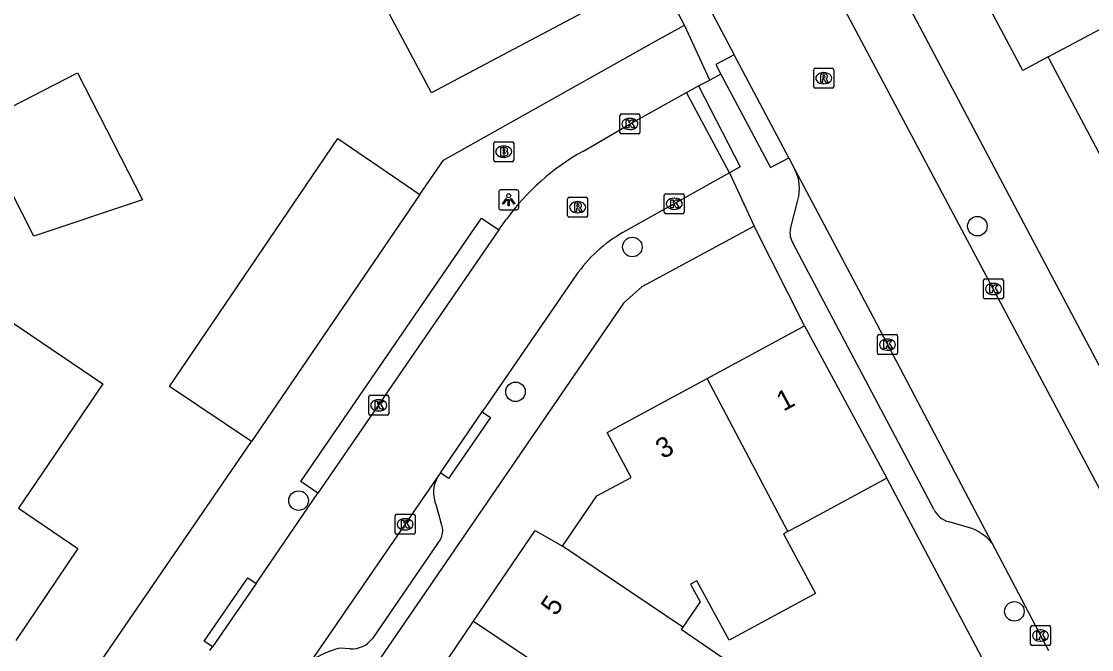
# Model space of a CAD drawing. Extents: x 157321 to 158827, y 386650 to 388532.
# Drawn here: x 157676.1 to 157729.7, y 387594.2 to 387625.6 of the extents above; entities that cross this region are included whole.
import ezdxf

# ---------------------------------------------------------------- set-up
doc = ezdxf.new("R2010")
doc.units = 0
for name, color, linetype in [('IMGEO_Boom', 7, 'Continuous'), ('IMGEO_Brandkraan', 7, 'Continuous'), ('IMGEO_Kolk', 7, 'Continuous'), ('IMGEO_Lichtpunt', 7, 'Continuous'), ('IMGEO_Pand', 7, 'Continuous'), ('IMGEO_Pand_nummerreeks', 7, 'Continuous'), ('IMGEO_Parkeervlak_open', 7, 'Continuous'), ('IMGEO_Rijbaan_lokaal_open', 7, 'Continuous'), ('IMGEO_Rioolput', 7, 'Continuous'), ('IMGEO_Voetpad_open', 7, 'Continuous')]:
    doc.layers.add(name, color=color, linetype=linetype)

msp = doc.modelspace()

# ---------------------------------------------------------------- linework, layer by layer
at = {"layer": 'IMGEO_Boom'}
for centre in [(157723.954, 387615.389), (157706.692, 387614.348), (157700.845, 387607.106), (157689.992, 387601.665), (157725.805, 387596.124)]:
    msp.add_circle(centre, 0.489, dxfattribs=at)
at = {"layer": 'IMGEO_Brandkraan'}
for p, q in [((157699.754, 387618.689), (157699.754, 387619.541)), ((157699.829, 387619.615), (157700.681, 387619.615)), ((157700.755, 387619.541), (157700.755, 387618.689)), ((157700.242, 387619.395), (157700.267, 387619.395)), ((157700.681, 387618.615), (157699.829, 387618.615)), ((157700.265, 387618.835), (157700.24, 387618.835))]:
    msp.add_line(p, q, dxfattribs=at)
for points in [[(157699.754, 387618.689), (157699.754, 387619.541)], [(157699.829, 387619.615), (157700.681, 387619.615)], [(157700.755, 387619.541), (157700.755, 387618.689)], [(157700.102, 387619.315), (157700.102, 387618.915), (157700.315, 387618.915)], [(157700.333, 387619.315), (157700.102, 387619.315)], [(157700.281, 387619.234), (157700.227, 387619.234), (157700.227, 387619.158)], [(157700.227, 387619.158), (157700.28, 387619.158)], [(157700.289, 387619.082), (157700.227, 387619.082), (157700.227, 387619.001)], [(157700.227, 387619.001), (157700.289, 387619.001)], [(157700.681, 387618.615), (157699.829, 387618.615)]]:
    msp.add_lwpolyline(points, dxfattribs=at)
for centre, radius, start, end in [((157699.831, 387619.539), 0.0765, 91.552, 178.448), ((157699.831, 387619.539), 0.0765, 91.552, 178.448), ((157700.679, 387619.539), 0.0765, 1.552, 88.448), ((157700.679, 387619.539), 0.0765, 1.552, 88.448), ((157700.282, 387619.196), 0.0379, 267.8285, 90.9355), ((157700.29, 387619.041), 0.0404, 269.8759, 90.5077), ((157700.321, 387619.166), 0.251, 268.6676, 293.5347), ((157700.337, 387619.17), 0.145, 59.4692, 91.5367), ((157700.362, 387619.217), 0.0922, 285.5137, 58.1501), ((157700.367, 387619.025), 0.105, 301.3115, 78.989), ((157699.831, 387618.691), 0.0765, 181.552, 268.448), ((157699.831, 387618.691), 0.0765, 181.552, 268.448), ((157700.679, 387618.691), 0.0765, 271.552, 358.448), ((157700.679, 387618.691), 0.0765, 271.552, 358.448)]:
    msp.add_arc(centre, radius, start, end, dxfattribs=at)
for centre, major_axis, ratio, start_param, end_param in [((157700.241, 387619.115), (-0.387, 0.002), 0.722429, 4.712389, 7.853982), ((157700.266, 387619.115), (-0.39, 0.002), 0.717154, 1.570796, 4.712389)]:
    msp.add_ellipse(centre, major_axis=major_axis, ratio=ratio, start_param=start_param, end_param=end_param, dxfattribs=at)
at = {"layer": 'IMGEO_Kolk'}
for p, q in [((157706.069, 387620.078), (157706.069, 387620.93)), ((157706.144, 387621.004), (157706.996, 387621.004)), ((157706.557, 387620.784), (157706.582, 387620.784)), ((157707.07, 387620.93), (157707.07, 387620.078)), ((157706.996, 387620.004), (157706.144, 387620.004)), ((157706.58, 387620.224), (157706.555, 387620.224)), ((157708.29, 387616.085), (157708.29, 387616.937)), ((157708.365, 387617.011), (157709.217, 387617.011)), ((157708.778, 387616.791), (157708.803, 387616.791)), ((157709.291, 387616.937), (157709.291, 387616.085)), ((157709.217, 387616.011), (157708.365, 387616.011)), ((157708.801, 387616.231), (157708.776, 387616.231)), ((157724.256, 387611.823), (157724.256, 387612.675)), ((157724.331, 387612.749), (157725.183, 387612.749)), ((157724.744, 387612.529), (157724.769, 387612.529)), ((157725.257, 387612.675), (157725.257, 387611.823)), ((157724.767, 387611.969), (157724.742, 387611.969)), ((157725.183, 387611.749), (157724.331, 387611.749)), ((157718.956, 387609.041), (157718.956, 387609.893)), ((157719.031, 387609.967), (157719.883, 387609.967)), ((157719.957, 387609.893), (157719.957, 387609.041)), ((157719.444, 387609.747), (157719.469, 387609.747)), ((157719.883, 387608.967), (157719.031, 387608.967)), ((157719.467, 387609.187), (157719.442, 387609.187)), ((157693.501, 387606.005), (157693.501, 387606.857)), ((157693.576, 387606.931), (157694.428, 387606.931)), ((157693.989, 387606.711), (157694.014, 387606.711)), ((157694.502, 387606.857), (157694.502, 387606.005)), ((157694.012, 387606.151), (157693.987, 387606.151)), ((157694.428, 387605.931), (157693.576, 387605.931)), ((157694.822, 387600.053), (157694.822, 387600.905)), ((157694.897, 387600.979), (157695.749, 387600.979)), ((157695.31, 387600.759), (157695.335, 387600.759)), ((157695.823, 387600.905), (157695.823, 387600.053)), ((157695.333, 387600.199), (157695.308, 387600.199)), ((157695.749, 387599.979), (157694.897, 387599.979)), ((157726.689, 387595.414), (157727.541, 387595.414)), ((157726.614, 387594.488), (157726.614, 387595.34)), ((157727.102, 387595.194), (157727.127, 387595.194)), ((157727.615, 387595.34), (157727.615, 387594.488)), ((157727.541, 387594.414), (157726.689, 387594.414)), ((157727.125, 387594.634), (157727.1, 387594.634))]:
    msp.add_line(p, q, dxfattribs=at)
for points in [[(157706.069, 387620.078), (157706.069, 387620.93)], [(157706.144, 387621.004), (157706.996, 387621.004)], [(157706.39, 387620.704), (157706.513, 387620.704), (157706.513, 387620.553), (157706.643, 387620.704), (157706.807, 387620.704), (157706.661, 387620.553), (157706.814, 387620.304), (157706.662, 387620.304), (157706.577, 387620.468), (157706.513, 387620.401), (157706.513, 387620.304), (157706.39, 387620.304), (157706.39, 387620.704)], [(157707.07, 387620.93), (157707.07, 387620.078)], [(157706.996, 387620.004), (157706.144, 387620.004)], [(157708.29, 387616.085), (157708.29, 387616.937)], [(157708.365, 387617.011), (157709.217, 387617.011)], [(157709.291, 387616.937), (157709.291, 387616.085)], [(157708.611, 387616.711), (157708.734, 387616.711), (157708.734, 387616.56), (157708.864, 387616.711), (157709.028, 387616.711), (157708.882, 387616.56), (157709.035, 387616.311), (157708.883, 387616.311), (157708.798, 387616.475), (157708.734, 387616.408), (157708.734, 387616.311), (157708.611, 387616.311), (157708.611, 387616.711)], [(157709.217, 387616.011), (157708.365, 387616.011)], [(157724.256, 387611.823), (157724.256, 387612.675)], [(157724.331, 387612.749), (157725.183, 387612.749)], [(157725.257, 387612.675), (157725.257, 387611.823)], [(157724.577, 387612.449), (157724.7, 387612.449), (157724.7, 387612.298), (157724.83, 387612.449), (157724.994, 387612.449), (157724.848, 387612.298), (157725.001, 387612.049), (157724.849, 387612.049), (157724.764, 387612.213), (157724.7, 387612.146), (157724.7, 387612.049), (157724.577, 387612.049), (157724.577, 387612.449)], [(157725.183, 387611.749), (157724.331, 387611.749)], [(157718.956, 387609.041), (157718.956, 387609.893)], [(157719.031, 387609.967), (157719.883, 387609.967)], [(157719.957, 387609.893), (157719.957, 387609.041)], [(157719.277, 387609.667), (157719.4, 387609.667), (157719.4, 387609.516), (157719.53, 387609.667), (157719.694, 387609.667), (157719.548, 387609.516), (157719.701, 387609.267), (157719.549, 387609.267), (157719.464, 387609.431), (157719.4, 387609.364), (157719.4, 387609.267), (157719.277, 387609.267), (157719.277, 387609.667)], [(157719.883, 387608.967), (157719.031, 387608.967)], [(157693.501, 387606.005), (157693.501, 387606.857)], [(157693.576, 387606.931), (157694.428, 387606.931)], [(157693.822, 387606.631), (157693.945, 387606.631), (157693.945, 387606.48), (157694.075, 387606.631), (157694.239, 387606.631), (157694.093, 387606.48), (157694.246, 387606.231), (157694.094, 387606.231), (157694.009, 387606.395), (157693.945, 387606.328), (157693.945, 387606.231), (157693.822, 387606.231), (157693.822, 387606.631)], [(157694.502, 387606.857), (157694.502, 387606.005)], [(157694.428, 387605.931), (157693.576, 387605.931)], [(157694.822, 387600.053), (157694.822, 387600.905)], [(157694.897, 387600.979), (157695.749, 387600.979)], [(157695.823, 387600.905), (157695.823, 387600.053)], [(157695.143, 387600.679), (157695.266, 387600.679), (157695.266, 387600.528), (157695.396, 387600.679), (157695.56, 387600.679), (157695.414, 387600.528), (157695.567, 387600.279), (157695.415, 387600.279), (157695.33, 387600.443), (157695.266, 387600.376), (157695.266, 387600.279), (157695.143, 387600.279), (157695.143, 387600.679)], [(157695.749, 387599.979), (157694.897, 387599.979)], [(157726.689, 387595.414), (157727.541, 387595.414)], [(157726.614, 387594.488), (157726.614, 387595.34)], [(157726.935, 387595.114), (157727.058, 387595.114), (157727.058, 387594.963), (157727.188, 387595.114), (157727.352, 387595.114), (157727.206, 387594.963), (157727.359, 387594.714), (157727.207, 387594.714), (157727.122, 387594.878), (157727.058, 387594.811), (157727.058, 387594.714), (157726.935, 387594.714), (157726.935, 387595.114)], [(157727.615, 387595.34), (157727.615, 387594.488)], [(157727.541, 387594.414), (157726.689, 387594.414)]]:
    msp.add_lwpolyline(points, dxfattribs=at)
for centre, start, end in [((157706.146, 387620.928), 91.552, 178.448), ((157706.146, 387620.928), 91.552, 178.448), ((157706.994, 387620.928), 1.552, 88.448), ((157706.994, 387620.928), 1.552, 88.448), ((157706.146, 387620.08), 181.552, 268.448), ((157706.146, 387620.08), 181.552, 268.448), ((157706.994, 387620.08), 271.552, 358.448), ((157706.994, 387620.08), 271.552, 358.448), ((157708.367, 387616.935), 91.552, 178.448), ((157708.367, 387616.935), 91.552, 178.448), ((157709.215, 387616.935), 1.552, 88.448), ((157709.215, 387616.935), 1.552, 88.448), ((157708.367, 387616.087), 181.552, 268.448), ((157708.367, 387616.087), 181.552, 268.448), ((157709.215, 387616.087), 271.552, 358.448), ((157709.215, 387616.087), 271.552, 358.448), ((157724.333, 387612.673), 91.552, 178.448), ((157724.333, 387612.673), 91.552, 178.448), ((157725.181, 387612.673), 1.552, 88.448), ((157725.181, 387612.673), 1.552, 88.448), ((157724.333, 387611.825), 181.552, 268.448), ((157724.333, 387611.825), 181.552, 268.448), ((157725.181, 387611.825), 271.552, 358.448), ((157725.181, 387611.825), 271.552, 358.448), ((157719.033, 387609.891), 91.552, 178.448), ((157719.033, 387609.891), 91.552, 178.448), ((157719.881, 387609.891), 1.552, 88.448), ((157719.881, 387609.891), 1.552, 88.448), ((157719.033, 387609.043), 181.552, 268.448), ((157719.033, 387609.043), 181.552, 268.448), ((157719.881, 387609.043), 271.552, 358.448), ((157719.881, 387609.043), 271.552, 358.448), ((157693.578, 387606.855), 91.552, 178.448), ((157693.578, 387606.855), 91.552, 178.448), ((157694.426, 387606.855), 1.552, 88.448), ((157694.426, 387606.855), 1.552, 88.448), ((157693.578, 387606.007), 181.552, 268.448), ((157693.578, 387606.007), 181.552, 268.448), ((157694.426, 387606.007), 271.552, 358.448), ((157694.426, 387606.007), 271.552, 358.448), ((157694.899, 387600.903), 91.552, 178.448), ((157694.899, 387600.903), 91.552, 178.448), ((157695.747, 387600.903), 1.552, 88.448), ((157695.747, 387600.903), 1.552, 88.448), ((157694.899, 387600.055), 181.552, 268.448), ((157694.899, 387600.055), 181.552, 268.448), ((157695.747, 387600.055), 271.552, 358.448), ((157695.747, 387600.055), 271.552, 358.448), ((157726.691, 387595.338), 91.552, 178.448), ((157726.691, 387595.338), 91.552, 178.448), ((157727.539, 387595.338), 1.552, 88.448), ((157727.539, 387595.338), 1.552, 88.448), ((157726.691, 387594.49), 181.552, 268.448), ((157726.691, 387594.49), 181.552, 268.448), ((157727.539, 387594.49), 271.552, 358.448), ((157727.539, 387594.49), 271.552, 358.448)]:
    msp.add_arc(centre, 0.0765, start, end, dxfattribs=at)
for centre, major_axis, ratio, start_param, end_param in [((157706.556, 387620.504), (-0.387, 0.002), 0.722429, 4.712389, 7.853982), ((157706.581, 387620.504), (-0.39, 0.002), 0.717154, 1.570796, 4.712389), ((157708.777, 387616.511), (-0.387, 0.002), 0.722429, 4.712389, 7.853982), ((157708.802, 387616.511), (-0.39, 0.002), 0.717154, 1.570796, 4.712389), ((157724.743, 387612.249), (-0.387, 0.002), 0.722429, 4.712389, 7.853982), ((157724.768, 387612.249), (-0.39, 0.002), 0.717154, 1.570796, 4.712389), ((157719.443, 387609.467), (-0.387, 0.002), 0.722429, 4.712389, 7.853982), ((157719.468, 387609.467), (-0.39, 0.002), 0.717154, 1.570796, 4.712389), ((157693.988, 387606.431), (-0.387, 0.002), 0.722429, 4.712389, 7.853982), ((157694.013, 387606.431), (-0.39, 0.002), 0.717154, 1.570796, 4.712389), ((157695.309, 387600.479), (-0.387, 0.002), 0.722429, 4.712389, 7.853982), ((157695.334, 387600.479), (-0.39, 0.002), 0.717154, 1.570796, 4.712389), ((157727.101, 387594.914), (-0.387, 0.002), 0.722429, 4.712389, 7.853982), ((157727.126, 387594.914), (-0.39, 0.002), 0.717154, 1.570796, 4.712389)]:
    msp.add_ellipse(centre, major_axis=major_axis, ratio=ratio, start_param=start_param, end_param=end_param, dxfattribs=at)
at = {"layer": 'IMGEO_Lichtpunt'}
for p, q in [((157700.008, 387617.11), (157700.008, 387616.303)), ((157700.008, 387617.11), (157700.008, 387616.303)), ((157700.91, 387617.205), (157700.102, 387617.205)), ((157700.91, 387617.205), (157700.102, 387617.205)), ((157701.004, 387616.303), (157701.004, 387617.11)), ((157701.004, 387616.303), (157701.004, 387617.11)), ((157700.102, 387616.209), (157700.91, 387616.209)), ((157700.102, 387616.209), (157700.91, 387616.209))]:
    msp.add_line(p, q, dxfattribs=at)
for points in [[(157700.382, 387616.774), (157700.421, 387616.746), (157700.233, 387616.484), (157700.195, 387616.511), (157700.382, 387616.774)], [(157700.594, 387616.746), (157700.632, 387616.773), (157700.819, 387616.511), (157700.78, 387616.483), (157700.594, 387616.746)], [(157700.484, 387616.726), (157700.531, 387616.726), (157700.531, 387616.404), (157700.484, 387616.404), (157700.484, 387616.726)]]:
    msp.add_lwpolyline(points, dxfattribs=at)
msp.add_circle((157700.507, 387616.908), 0.0994, dxfattribs=at)
for centre, start, end in [((157700.102, 387617.11), 90, 180), ((157700.102, 387617.11), 90, 180), ((157700.91, 387617.11), 0, 90), ((157700.91, 387617.11), 0, 90), ((157700.102, 387616.303), 180, 270), ((157700.102, 387616.303), 180, 270), ((157700.91, 387616.303), 270, 0), ((157700.91, 387616.303), 270, 360)]:
    msp.add_arc(centre, 0.0946, start, end, dxfattribs=at)
at = {"layer": 'IMGEO_Pand'}
for points in [[(157694.636, 387636.283), (157696.505, 387632.753), (157698.132, 387633.614), (157700.593, 387634.917), (157700.897, 387634.343), (157700.633, 387634.203), (157702.386, 387630.888), (157702.652, 387631.029), (157705.042, 387626.514), (157698.776, 387623.196), (157696.641, 387622.066), (157692.328, 387630.163), (157689.141, 387628.499), (157686.993, 387632.562)], [(157727.501, 387623.859), (157726.228, 387623.18), (157723.396, 387628.511), (157724.662, 387629.181)], [(157727.501, 387623.859), (157734.991, 387627.855)], [(157730.322, 387618.545), (157727.568, 387623.732), (157727.501, 387623.859)], [(157678.933, 387623.056), (157682.186, 387616.71), (157676.751, 387614.891), (157673.891, 387620.471), (157678.933, 387623.056)], [(157666.998, 387600.692), (157667.045, 387600.761), (157674.312, 387611.492), (157676.06, 387610.308), (157680.199, 387607.505), (157677.721, 387603.845), (157675.982, 387601.278), (157678.954, 387599.264), (157675.839, 387594.663)], [(157710.429, 387607.767), (157715.302, 387610.401)], [(157715.302, 387610.401), (157719.417, 387602.787)], [(157703.199, 387599.386), (157704.915, 387601.899), (157706.636, 387602.828), (157705.427, 387605.064), (157710.429, 387607.767)], [(157714.466, 387600.111), (157710.429, 387607.767)], [(157719.417, 387602.787), (157715.019, 387600.41), (157714.466, 387600.111)], [(157698.751, 387595.629), (157701.836, 387600.175), (157703.199, 387599.386)], [(157714.466, 387600.111), (157714.252, 387599.996), (157715.862, 387597.016), (157711.531, 387594.676), (157709.921, 387597.655), (157709.609, 387597.486), (157710.084, 387596.608), (157709.21, 387595.329)], [(157709.21, 387595.329), (157703.199, 387599.386)], [(157695.719, 387591.162), (157698.751, 387595.629)], [(157698.751, 387595.629), (157707.759, 387589.578), (157710.13, 387587.931)], [(157709.21, 387595.329), (157709.14, 387595.226), (157710.829, 387594.072), (157713.365, 387592.357), (157710.294, 387587.817), (157710.13, 387587.931)]]:
    msp.add_lwpolyline(points, dxfattribs=at)
at = {"layer": 'IMGEO_Parkeervlak_open'}
msp.add_lwpolyline([(157687.645, 387604.627), (157683.532, 387607.372), (157691.95, 387619.773), (157696.06, 387616.975)], dxfattribs=at)
at = {"layer": 'IMGEO_Rijbaan_lokaal_open'}
for points in [[(157735.466, 387592.089), (157729.998, 387602.392), (157713.019, 387634.314), (157706.841, 387645.947), (157703.178, 387652.824)], [(157704.707, 387637.298), (157708.819, 387629.59), (157711.79, 387623.962)], [(157714.525, 387618.81), (157711.79, 387623.962)], [(157709.408, 387622.072), (157710.003, 387622.401)], [(157710.003, 387622.401), (157712.088, 387618.361), (157711.546, 387618.057)], [(157704.213, 387619.132), (157706.579, 387620.507), (157709.408, 387622.072)], [(157711.546, 387618.057), (157709.408, 387622.072)], [(157714.525, 387618.81), (157714.825, 387618.222)], [(157711.546, 387618.057), (157706.219, 387615.068)], [(157714.825, 387618.222), (157718.741, 387610.836), (157724.678, 387599.557)], [(157700.009, 387615.204), (157700.397, 387615.747)], [(157700.009, 387615.204), (157690.96, 387602.031)], [(157703.869, 387612.921), (157699.183, 387606.1)], [(157697.087, 387603.049), (157699.183, 387606.1)], [(157696.959, 387602.862), (157690.592, 387593.594)], [(157697.087, 387603.049), (157696.959, 387602.862)], [(157687.865, 387597.52), (157690.96, 387602.031)], [(157724.678, 387599.557), (157727.511, 387594.161)], [(157687.865, 387597.52), (157685.678, 387594.352)], [(157685.555, 387594.174), (157685.678, 387594.352)]]:
    msp.add_lwpolyline(points, dxfattribs=at)
for centre, radius, start, end in [((157710.159, 387608.585), 12.108, 119.4141, 143.7354), ((157709.67, 387608.932), 7.04, 119.3494, 145.4813)]:
    msp.add_arc(centre, radius, start, end, dxfattribs=at)
at = {"layer": 'IMGEO_Rioolput'}
for p, q in [((157715.765, 387622.365), (157715.765, 387623.217)), ((157715.84, 387623.291), (157716.692, 387623.291)), ((157716.766, 387623.217), (157716.766, 387622.365)), ((157716.253, 387623.071), (157716.278, 387623.071)), ((157716.692, 387622.291), (157715.84, 387622.291)), ((157716.276, 387622.511), (157716.251, 387622.511)), ((157703.53, 387616.837), (157704.382, 387616.837)), ((157703.455, 387615.911), (157703.455, 387616.763)), ((157703.943, 387616.617), (157703.968, 387616.617)), ((157704.456, 387616.763), (157704.456, 387615.911)), ((157704.382, 387615.837), (157703.53, 387615.837)), ((157703.966, 387616.057), (157703.941, 387616.057))]:
    msp.add_line(p, q, dxfattribs=at)
for points in [[(157715.765, 387622.365), (157715.765, 387623.217)], [(157715.84, 387623.291), (157716.692, 387623.291)], [(157716.766, 387623.217), (157716.766, 387622.365)], [(157716.354, 387622.989), (157716.102, 387622.991), (157716.102, 387622.591)], [(157716.102, 387622.591), (157716.226, 387622.591), (157716.226, 387622.753), (157716.237, 387622.753)], [(157716.28, 387622.91), (157716.226, 387622.91), (157716.226, 387622.829)], [(157716.226, 387622.829), (157716.278, 387622.829)], [(157716.284, 387622.724), (157716.355, 387622.591), (157716.495, 387622.591), (157716.43, 387622.717)], [(157716.692, 387622.291), (157715.84, 387622.291)], [(157703.53, 387616.837), (157704.382, 387616.837)], [(157703.455, 387615.911), (157703.455, 387616.763)], [(157704.044, 387616.535), (157703.792, 387616.537), (157703.792, 387616.137)], [(157703.792, 387616.137), (157703.916, 387616.137), (157703.916, 387616.299), (157703.927, 387616.299)], [(157703.97, 387616.456), (157703.916, 387616.456), (157703.916, 387616.375)], [(157703.916, 387616.375), (157703.968, 387616.375)], [(157703.974, 387616.27), (157704.045, 387616.137), (157704.185, 387616.137), (157704.12, 387616.263)], [(157704.456, 387616.763), (157704.456, 387615.911)], [(157704.382, 387615.837), (157703.53, 387615.837)]]:
    msp.add_lwpolyline(points, dxfattribs=at)
for centre, radius, start, end in [((157715.842, 387623.215), 0.0765, 91.552, 178.448), ((157715.842, 387623.215), 0.0765, 91.552, 178.448), ((157716.69, 387623.215), 0.0765, 1.552, 88.448), ((157716.69, 387623.215), 0.0765, 1.552, 88.448), ((157716.236, 387622.7), 0.0533, 26.0293, 88.6989), ((157716.262, 387623.018), 0.19, 274.7715, 282.9687), ((157716.286, 387622.814), 0.0964, 77.0061, 93.1865), ((157716.3, 387622.871), 0.0378, 276.6634, 79.6772), ((157716.353, 387622.879), 0.109, 350.3612, 89.416), ((157716.351, 387622.879), 0.112, 277.5842, 350.9817), ((157716.335, 387622.664), 0.108, 29.5134, 73.7905), ((157715.842, 387622.367), 0.0765, 181.552, 268.448), ((157715.842, 387622.367), 0.0765, 181.552, 268.448), ((157716.69, 387622.367), 0.0765, 271.552, 358.448), ((157716.69, 387622.367), 0.0765, 271.552, 358.448), ((157703.532, 387616.761), 0.0765, 91.552, 178.448), ((157703.532, 387616.761), 0.0765, 91.552, 178.448), ((157704.38, 387616.761), 0.0765, 1.552, 88.448), ((157704.38, 387616.761), 0.0765, 1.552, 88.448), ((157703.926, 387616.246), 0.0533, 26.0293, 88.6989), ((157703.952, 387616.564), 0.19, 274.7715, 282.9687), ((157703.976, 387616.36), 0.0964, 77.0061, 93.1865), ((157703.99, 387616.417), 0.0378, 276.6634, 79.6772), ((157704.043, 387616.425), 0.109, 350.3612, 89.416), ((157704.041, 387616.425), 0.112, 277.5842, 350.9817), ((157704.025, 387616.21), 0.108, 29.5134, 73.7905), ((157703.532, 387615.913), 0.0765, 181.552, 268.448), ((157703.532, 387615.913), 0.0765, 181.552, 268.448), ((157704.38, 387615.913), 0.0765, 271.552, 358.448), ((157704.38, 387615.913), 0.0765, 271.552, 358.448)]:
    msp.add_arc(centre, radius, start, end, dxfattribs=at)
for centre, major_axis, ratio, start_param, end_param in [((157716.252, 387622.791), (-0.387, 0.002), 0.722429, 4.712389, 7.853982), ((157716.277, 387622.791), (-0.39, 0.002), 0.717154, 1.570796, 4.712389), ((157703.942, 387616.337), (-0.387, 0.002), 0.722429, 4.712389, 7.853982), ((157703.967, 387616.337), (-0.39, 0.002), 0.717154, 1.570796, 4.712389)]:
    msp.add_ellipse(centre, major_axis=major_axis, ratio=ratio, start_param=start_param, end_param=end_param, dxfattribs=at)
at = {"layer": 'IMGEO_Voetpad_open'}
for points in [[(157709.303, 387625.45), (157695.172, 387652.085), (157692.4, 387657.299), (157692.336, 387657.419), (157689.915, 387661.997), (157689.894, 387662.037), (157688.503, 387664.651), (157680.127, 387680.393), (157678.819, 387682.868), (157676.207, 387683.552)], [(157705.154, 387655.407), (157705.212, 387655.297), (157737.182, 387594.934), (157737.199, 387594.901)], [(157696.06, 387616.975), (157697.238, 387618.697), (157707.692, 387624.565), (157709.303, 387625.45)], [(157710.561, 387622.698), (157709.303, 387625.45)], [(157711.79, 387623.962), (157710.871, 387623.474), (157711.124, 387622.997)], [(157710.003, 387622.401), (157710.561, 387622.698)], [(157711.124, 387622.997), (157710.561, 387622.698)], [(157711.124, 387622.997), (157713.606, 387618.322), (157714.525, 387618.81)], [(157711.546, 387618.057), (157712.78, 387615.384)], [(157696.06, 387616.975), (157687.645, 387604.627)], [(157714.598, 387615.265), (157714.974, 387616.695)], [(157690.96, 387602.031), (157690.103, 387602.62), (157699.152, 387615.793), (157700.009, 387615.204)], [(157712.78, 387615.384), (157707.158, 387612.356), (157706.257, 387611.54), (157692.204, 387591.043), (157667.746, 387555.368)], [(157715.302, 387610.401), (157712.78, 387615.384)], [(157721.787, 387601.203), (157717.196, 387609.885), (157714.739, 387614.519)], [(157699.183, 387606.1), (157699.594, 387605.816), (157697.498, 387602.765), (157697.087, 387603.049)], [(157656.917, 387559.848), (157687.645, 387604.627)], [(157727.739, 387587.082), (157719.417, 387602.787)], [(157696.88, 387601.427), (157697.111, 387600.577)], [(157723.512, 387600.322), (157722.535, 387600.604)], [(157696.948, 387599.523), (157693.686, 387594.766)], [(157685.678, 387594.352), (157685.267, 387594.636), (157687.454, 387597.804), (157687.865, 387597.52)], [(157692.57, 387594.255), (157692.062, 387594.279)]]:
    msp.add_lwpolyline(points, dxfattribs=at)
for centre, radius, start, end in [((157712.941, 387617.267), 2.112, 344.277, 26.8692), ((157715.565, 387615.061), 0.988, 168.1172, 213.2891), ((157698.316, 387602.068), 1.573, 149.6616, 204.0362), ((157722.827, 387601.735), 1.168, 207.0844, 255.5399), ((157696.279, 387600.166), 0.928, 316.1347, 26.2832), ((157722.818, 387597.994), 2.43, 40.0535, 73.4096), ((157692.665, 387595.523), 1.271, 265.7366, 323.468), ((157692.799, 387590.777), 3.579, 101.8905, 128.0793)]:
    msp.add_arc(centre, radius, start, end, dxfattribs=at)

# ---------------------------------------------------------------- texts
at = {"layer": 'IMGEO_Pand_nummerreeks'}
for s, rotation, p in [('1', 28.3893, (157714.251, 387606.105)), ('3', 28.3843, (157708.206, 387603.725)), ('5', 55.8405, (157702.867, 387595.851))]:
    msp.add_text(s, height=1, rotation=rotation, dxfattribs=at).set_placement(p)

doc.saveas('drawing.dxf')
